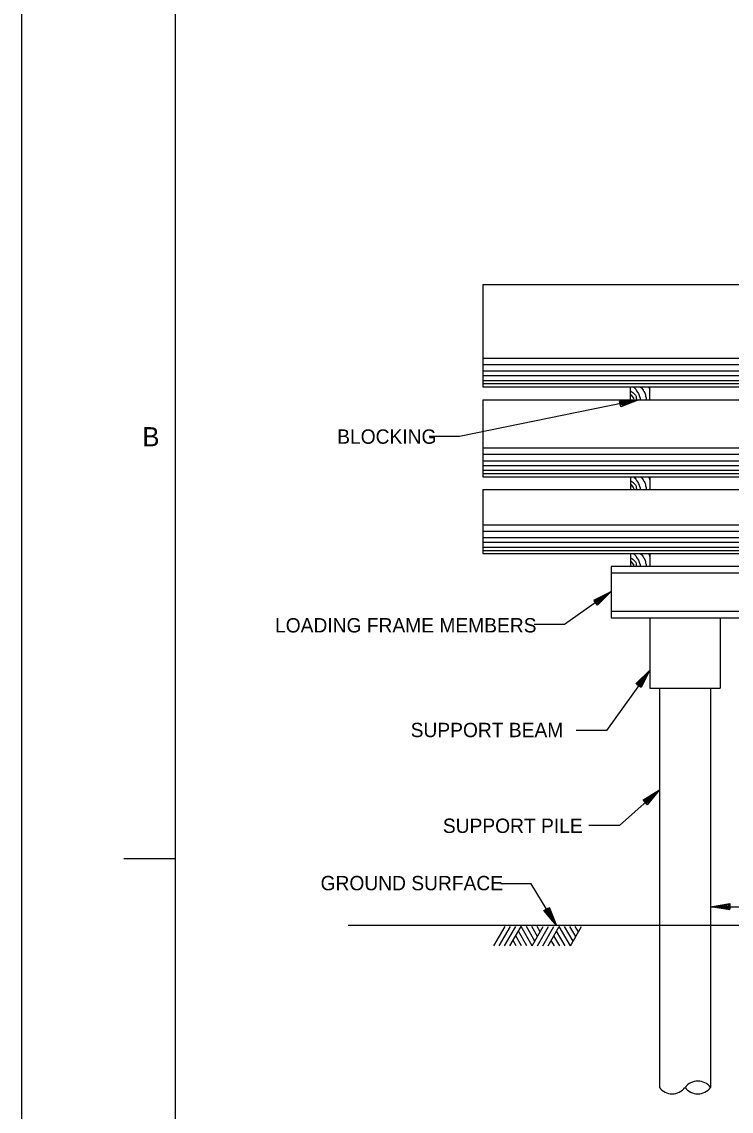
# Model space of a CAD drawing. Extents: x 22378.6 to 22422.6, y 22377.7 to 22411.7.
# Drawn here: x 22378.63 to 22385.54, y 22383.94 to 22394.56 of the extents above; entities that cross this region are included whole.
import ezdxf

# ---------------------------------------------------------------- set-up
doc = ezdxf.new("R2010")
doc.units = 0
for name, color, linetype in [('Level 1', 7, 'Continuous'), ('Level 10', 7, 'Continuous'), ('Level 2', 7, 'Continuous'), ('Level 4', 7, 'Continuous'), ('Level 7', 7, 'Continuous'), ('Level 9', 7, 'Continuous')]:
    doc.layers.add(name, color=color, linetype=linetype)

msp = doc.modelspace()

# ---------------------------------------------------------------- linework, layer by layer
at = {"layer": 'Level 1'}
for p, q in [((22383.125, 22391.061), (22389.375, 22391.061)), ((22383.125, 22391.03), (22389.375, 22391.03)), ((22384.594, 22390.863), (22384.594, 22390.863)), ((22384.645, 22390.873), (22384.645, 22390.873)), ((22383.125, 22390.186), (22389.375, 22390.186)), ((22383.125, 22390.154), (22389.375, 22390.154)), ((22383.125, 22389.436), (22389.375, 22389.436)), ((22383.125, 22389.404), (22389.375, 22389.404)), ((22384.333, 22388.972), (22384.333, 22388.972)), ((22384.375, 22389.002), (22384.375, 22389.002)), ((22384.72, 22388.194), (22384.72, 22388.194)), ((22384.75, 22388.236), (22384.75, 22388.236)), ((22384.805, 22387.037), (22384.805, 22387.037)), ((22384.844, 22387.071), (22384.844, 22387.071)), ((22385.344, 22385.929), (22387.203, 22385.929)), ((22385.344, 22385.929), (22385.344, 22385.929)), ((22385.396, 22385.929), (22385.396, 22385.929)), ((22383.232, 22385.549), (22383.34, 22385.736)), ((22383.284, 22385.549), (22383.392, 22385.736)), ((22383.336, 22385.549), (22383.444, 22385.736)), ((22383.388, 22385.549), (22383.496, 22385.736)), ((22383.605, 22385.549), (22383.496, 22385.736)), ((22383.631, 22385.594), (22383.548, 22385.736)), ((22383.657, 22385.639), (22383.6, 22385.736)), ((22383.605, 22385.549), (22383.713, 22385.736)), ((22383.683, 22385.684), (22383.652, 22385.736)), ((22383.657, 22385.549), (22383.765, 22385.736)), ((22383.708, 22385.549), (22383.817, 22385.736)), ((22383.76, 22385.549), (22383.869, 22385.736)), ((22383.815, 22385.793), (22383.815, 22385.793)), ((22383.842, 22385.748), (22383.842, 22385.748)), ((22383.977, 22385.549), (22383.869, 22385.736)), ((22384.003, 22385.594), (22383.921, 22385.736)), ((22384.029, 22385.639), (22383.973, 22385.736)), ((22383.977, 22385.549), (22384.085, 22385.736)), ((22384.055, 22385.684), (22384.025, 22385.736)), ((22383.501, 22385.549), (22383.444, 22385.646)), ((22383.553, 22385.549), (22383.47, 22385.691)), ((22383.873, 22385.549), (22383.817, 22385.646)), ((22383.925, 22385.549), (22383.843, 22385.691)), ((22383.449, 22385.549), (22383.418, 22385.601)), ((22383.821, 22385.549), (22383.791, 22385.601))]:
    msp.add_line(p, q, dxfattribs=at)
msp.add_lwpolyline([(22378.629, 22411.659), (22422.645, 22411.659), (22422.645, 22377.651), (22378.629, 22377.651)], close=True, dxfattribs=at)
for points in [[(22384.565, 22390.956), (22384.575, 22390.95), (22384.586, 22390.943), (22384.593, 22390.938), (22384.602, 22390.929), (22384.611, 22390.918), (22384.617, 22390.904), (22384.619, 22390.89), (22384.62, 22390.878)], [(22384.591, 22390.995), (22384.6, 22390.991), (22384.607, 22390.983), (22384.614, 22390.975), (22384.623, 22390.96), (22384.632, 22390.948), (22384.642, 22390.933), (22384.648, 22390.916), (22384.652, 22390.904), (22384.656, 22390.89), (22384.658, 22390.872)], [(22384.659, 22390.996), (22384.671, 22390.989), (22384.68, 22390.977), (22384.687, 22390.966), (22384.694, 22390.955), (22384.702, 22390.942), (22384.706, 22390.931), (22384.709, 22390.92), (22384.71, 22390.908), (22384.715, 22390.893), (22384.716, 22390.881), (22384.715, 22390.874)], [(22384.737, 22390.998), (22384.744, 22390.988), (22384.75, 22390.968)], [(22384.645, 22390.873), (22382.895, 22390.516), (22382.599, 22390.516)], [(22384.455, 22390.866), (22384.645, 22390.873), (22384.468, 22390.805), (22384.457, 22390.857), (22384.594, 22390.863), (22384.474, 22390.817), (22384.467, 22390.85), (22384.545, 22390.853), (22384.479, 22390.828), (22384.477, 22390.842), (22384.494, 22390.842)], [(22384.564, 22390.924), (22384.57, 22390.921), (22384.574, 22390.914), (22384.579, 22390.906), (22384.582, 22390.902), (22384.589, 22390.893), (22384.594, 22390.881)], [(22384.591, 22390.12), (22384.6, 22390.116), (22384.607, 22390.108), (22384.614, 22390.1), (22384.623, 22390.085), (22384.632, 22390.073), (22384.642, 22390.058), (22384.648, 22390.041), (22384.652, 22390.029), (22384.656, 22390.015), (22384.658, 22389.997)], [(22384.659, 22390.121), (22384.671, 22390.114), (22384.68, 22390.102), (22384.687, 22390.091), (22384.694, 22390.08), (22384.702, 22390.067), (22384.706, 22390.055), (22384.709, 22390.045), (22384.71, 22390.033), (22384.715, 22390.018), (22384.716, 22390.006), (22384.715, 22389.999)], [(22384.737, 22390.123), (22384.744, 22390.113), (22384.75, 22390.093)], [(22384.564, 22390.049), (22384.57, 22390.046), (22384.574, 22390.039), (22384.579, 22390.031), (22384.582, 22390.027), (22384.589, 22390.018), (22384.594, 22390.006)], [(22384.565, 22390.081), (22384.575, 22390.075), (22384.586, 22390.068), (22384.593, 22390.063), (22384.602, 22390.054), (22384.611, 22390.043), (22384.617, 22390.029), (22384.619, 22390.015), (22384.62, 22390.003)], [(22384.591, 22389.37), (22384.6, 22389.366), (22384.607, 22389.358), (22384.614, 22389.35), (22384.623, 22389.335), (22384.632, 22389.323), (22384.642, 22389.308), (22384.648, 22389.291), (22384.652, 22389.279), (22384.656, 22389.265), (22384.658, 22389.247)], [(22384.659, 22389.371), (22384.671, 22389.364), (22384.68, 22389.352), (22384.687, 22389.341), (22384.694, 22389.33), (22384.702, 22389.317), (22384.706, 22389.305), (22384.709, 22389.295), (22384.71, 22389.283), (22384.715, 22389.268), (22384.716, 22389.256), (22384.715, 22389.249)], [(22384.737, 22389.373), (22384.744, 22389.363), (22384.75, 22389.343)], [(22384.564, 22389.299), (22384.57, 22389.296), (22384.574, 22389.289), (22384.579, 22389.281), (22384.582, 22389.277), (22384.589, 22389.268), (22384.594, 22389.256)], [(22384.565, 22389.331), (22384.575, 22389.325), (22384.586, 22389.318), (22384.593, 22389.313), (22384.602, 22389.304), (22384.611, 22389.293), (22384.617, 22389.279), (22384.619, 22389.265), (22384.62, 22389.253)], [(22384.375, 22389.002), (22383.919, 22388.682), (22383.623, 22388.682)], [(22384.204, 22388.92), (22384.375, 22389.002), (22384.24, 22388.869), (22384.21, 22388.913), (22384.333, 22388.972), (22384.241, 22388.882), (22384.221, 22388.91), (22384.292, 22388.944), (22384.242, 22388.895), (22384.234, 22388.907), (22384.249, 22388.914)], [(22384.75, 22388.236), (22384.329, 22387.647), (22384.032, 22387.647)], [(22384.616, 22388.102), (22384.75, 22388.236), (22384.667, 22388.066), (22384.624, 22388.097), (22384.72, 22388.194), (22384.663, 22388.078), (22384.635, 22388.098), (22384.691, 22388.153), (22384.66, 22388.091), (22384.648, 22388.099), (22384.661, 22388.111)], [(22384.844, 22387.071), (22384.455, 22386.722), (22384.158, 22386.722)], [(22384.684, 22386.97), (22384.844, 22387.071), (22384.725, 22386.923), (22384.69, 22386.963), (22384.805, 22387.037), (22384.725, 22386.936), (22384.702, 22386.962), (22384.768, 22387.003), (22384.724, 22386.949), (22384.715, 22386.959), (22384.729, 22386.969)], [(22383.842, 22385.748), (22383.595, 22386.153), (22383.298, 22386.153)], [(22385.531, 22385.898), (22385.344, 22385.929), (22385.531, 22385.96), (22385.531, 22385.907), (22385.396, 22385.929), (22385.523, 22385.95), (22385.523, 22385.916), (22385.446, 22385.929), (22385.515, 22385.94), (22385.515, 22385.926), (22385.498, 22385.929)], [(22383.771, 22385.924), (22383.842, 22385.748), (22383.718, 22385.892), (22383.763, 22385.919), (22383.815, 22385.793), (22383.731, 22385.89), (22383.76, 22385.908), (22383.789, 22385.835), (22383.743, 22385.888), (22383.755, 22385.896), (22383.762, 22385.88)]]:
    msp.add_lwpolyline(points, dxfattribs=at)
at = {"layer": 'Level 10'}
msp.add_line((22379.625, 22386.399), (22380.129, 22386.399), dxfattribs=at)
at = {"layer": 'Level 2'}
for p, q in [((22383.125, 22391.28), (22389.375, 22391.28)), ((22383.125, 22391.217), (22389.375, 22391.217)), ((22383.125, 22391.155), (22389.375, 22391.155)), ((22383.125, 22391.108), (22389.375, 22391.108)), ((22384.563, 22390.873), (22384.563, 22390.998)), ((22384.75, 22390.873), (22384.75, 22390.998)), ((22383.125, 22390.405), (22389.375, 22390.405)), ((22383.125, 22390.342), (22389.375, 22390.342)), ((22383.125, 22390.279), (22389.375, 22390.279)), ((22383.125, 22390.233), (22389.375, 22390.233)), ((22384.563, 22390.123), (22384.563, 22389.998)), ((22384.75, 22390.123), (22384.75, 22389.998)), ((22383.125, 22389.654), (22389.375, 22389.654)), ((22383.125, 22389.592), (22389.375, 22389.592)), ((22383.125, 22389.529), (22389.375, 22389.529)), ((22383.125, 22389.483), (22389.375, 22389.483)), ((22384.563, 22389.373), (22384.563, 22389.248)), ((22384.75, 22389.373), (22384.75, 22389.248)), ((22384.375, 22389.186), (22389.375, 22389.186)), ((22384.375, 22388.811), (22389.375, 22388.811)), ((22389.375, 22385.748), (22381.81, 22385.748)), ((22384.844, 22385.748), (22384.844, 22384.167)), ((22385.344, 22385.748), (22385.344, 22384.167))]:
    msp.add_line(p, q, dxfattribs=at)
for centre, start, end in [((22384.969, 22384.261), 216.8699, 323.1301), ((22385.219, 22384.074), 36.8623, 143.1377), ((22385.219, 22384.261), 216.8699, 323.1301)]:
    msp.add_arc(centre, 0.156, start, end, dxfattribs=at)
at = {"layer": 'Level 7'}
for p, q in [((22383.125, 22391.998), (22389.375, 22391.998)), ((22383.125, 22391.998), (22383.125, 22390.998)), ((22383.125, 22390.998), (22389.375, 22390.998)), ((22383.125, 22390.873), (22389.375, 22390.873)), ((22383.125, 22390.873), (22383.125, 22390.123)), ((22383.125, 22390.123), (22389.375, 22390.123)), ((22383.125, 22389.998), (22389.375, 22389.998)), ((22383.125, 22389.998), (22383.125, 22389.373)), ((22383.125, 22389.373), (22389.375, 22389.373)), ((22389.375, 22389.248), (22384.375, 22389.248)), ((22384.375, 22389.248), (22384.375, 22388.748)), ((22384.375, 22388.748), (22389.375, 22388.748)), ((22384.75, 22388.748), (22384.75, 22388.061)), ((22385.438, 22388.748), (22385.438, 22388.061)), ((22384.75, 22388.061), (22385.438, 22388.061)), ((22384.844, 22388.061), (22384.844, 22385.748)), ((22385.344, 22388.061), (22385.344, 22385.748))]:
    msp.add_line(p, q, dxfattribs=at)
at = {"layer": 'Level 9'}
msp.add_line((22380.129, 22378.155), (22380.129, 22411.155), dxfattribs=at)

# ---------------------------------------------------------------- texts
at = {"layer": 'Level 1'}
msp.add_text('B', height=0.187, dxfattribs=at).set_placement((22379.805, 22390.419))
at = {"layer": 'Level 4'}
for s, p in [('BLOCKING', (22381.704, 22390.444)), ('LOADING FRAME MEMBERS', (22381.098, 22388.604)), ('SUPPORT BEAM', (22382.42, 22387.583)), ('SUPPORT PILE', (22382.734, 22386.649)), ('GROUND SURFACE', (22381.542, 22386.09))]:
    msp.add_text(s, height=0.14, dxfattribs=at).set_placement(p)

doc.saveas('drawing.dxf')
